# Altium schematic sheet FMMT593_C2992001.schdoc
size 127 x 101 mm
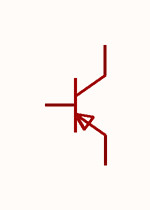
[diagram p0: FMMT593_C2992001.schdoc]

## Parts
Q?  fmmt593  [SOT-23-3_L2.9-W1.3-P0.95-LS2.4-BR]  (value not drawn)

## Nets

Not connected (* = marked no-connect by the designer): Q? 1(B) 2(E) 3(C)

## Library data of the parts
Q? = fmmt593: 晶体管类型:PNP;集电极电流(Ic):1A;集射极击穿电压(Vceo):100V;耗散功率(Pd):250mW;直流电流增益(hFE):100;; Manufacturer: CJ(江苏长电/长晶); Symbol: FMMT593_C2992001; AddInBom: yes; ModelId: c62791f0466c4ae2a892c056b845b0ca; ModelName: SOT-23-3P_L2.9-W1.3-H1.0-LS2.4-P0.95; ModelTransform: 98.425,114.173,0,180,0,0,0.0005,-0.0005,0; type: PNP; Current - Collector(Ic): 1A; Collector - Emitter Voltage VCEO: 100V; Pd - Power Dissipation: 250mW; DC Current Gain: 100; Transition frequency(fT): 50MHz; Current - Collector Cutoff: 100nA; Vce Saturation(VCE(sat)): 300mV; Emitter-Base Voltage(Vebo): 5V; Number: 1个PNP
